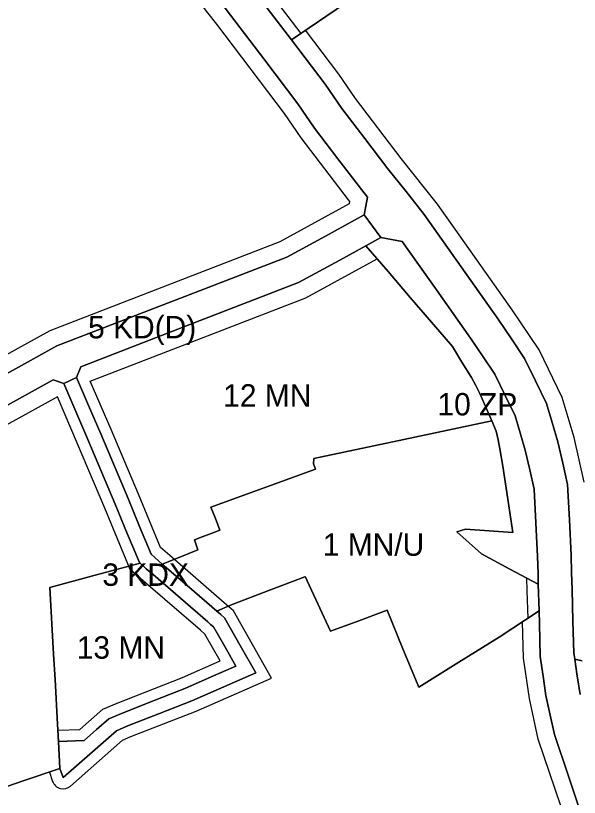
# Model space of a CAD drawing. Extents: x 7423691 to 7425475, y 5552085 to 5554331.
# Drawn here: x 7424385.3 to 7424586.6, y 5552384.7 to 5552663.9 of the extents above; entities that cross this region are included whole.
import ezdxf

# ---------------------------------------------------------------- set-up
doc = ezdxf.new("R2010")
doc.units = 0
for name, color, linetype in [('linia_zabudowy_nieprzekraczalna', 7, 'Continuous'), ('linie_rozgraniczajace', 7, 'Continuous'), ('oznaczenia_przeznaczen', 7, 'Continuous')]:
    doc.layers.add(name, color=color, linetype=linetype)

msp = doc.modelspace()

# ---------------------------------------------------------------- linework, layer by layer
at = {"layer": 'linia_zabudowy_nieprzekraczalna'}
for points in [[(7424378.95, 5552840.23), (7424386.33, 5552813.96), (7424395.24, 5552774.37), (7424402.55, 5552750.36), (7424407.19, 5552738.02), (7424416.77, 5552717.96), (7424423.18, 5552706.49), (7424436.27, 5552687.89), (7424453.78, 5552664.96), (7424456.99, 5552660.89), (7424481.21, 5552628.98), (7424487.16, 5552620.28), (7424504.05, 5552598.12), (7424504.53, 5552597.51), (7424504.36, 5552596.69), (7424479.58, 5552583.13), (7424397.48, 5552551.4), (7424333.75, 5552516.27)], [(7424434.7, 5552731.45), (7424436.32, 5552728.07), (7424441.82, 5552718.22), (7424454.01, 5552700.91), (7424471.16, 5552678.45), (7424474.39, 5552674.35), (7424487.13, 5552657.57)], [(7424588.36, 5552497.25), (7424584.74, 5552513.23), (7424580.52, 5552527.54), (7424572.26, 5552544.52), (7424562.6, 5552558.89), (7424536, 5552596.56), (7424522.97, 5552612.88), (7424506.62, 5552634.34), (7424500.68, 5552643.02), (7424488.78, 5552658.7)], [(7424404.9, 5552388.73), (7424423.44, 5552405.07), (7424426.46, 5552406.37), (7424449.78, 5552415.52), (7424476.7, 5552427.27), (7424463.04, 5552451.36), (7424459.75, 5552454.21), (7424440.29, 5552471.03), (7424436.98, 5552473.92), (7424429.13, 5552492.94), (7424419.34, 5552516.1), (7424411.91, 5552533.39), (7424488.87, 5552563.13), (7424514.37, 5552577.09)], [(7424400.4, 5552408.64), (7424408.18, 5552408.95), (7424416.39, 5552416.19), (7424421.51, 5552418.39), (7424444.81, 5552427.53), (7424458.27, 5552433.41), (7424452.84, 5552443), (7424451.24, 5552444.38), (7424431.75, 5552461.23), (7424426.13, 5552466.13), (7424417.13, 5552487.94), (7424407.39, 5552511.01), (7424400.18, 5552527.77), (7424354.16, 5552502.4)], [(7424568.27, 5552448.72), (7424568.01, 5552458.45), (7424567.89, 5552463.01)], [(7424580.08, 5552381.26), (7424571.92, 5552405.53), (7424568.75, 5552420), (7424566.65, 5552434.46), (7424566.31, 5552447.41)], [(7424397.31, 5552393.73), (7424398.48, 5552390.4)]]:
    msp.add_lwpolyline(points, dxfattribs=at)
msp.add_arc((7424402.25, 5552391.73), 4, 199.4247, 311.4135, dxfattribs=at)
at = {"layer": 'linie_rozgraniczajace'}
for points in [[(7424506.02, 5552670.56), (7424483.83, 5552655.3), (7424471.23, 5552671.9)], [(7424471.23, 5552671.9), (7424483.83, 5552655.3), (7424495.81, 5552639.51), (7424501.75, 5552630.82), (7424510, 5552620)], [(7424483.83, 5552655.3), (7424506.02, 5552670.56)], [(7424458.52, 5552668.64), (7424473.91, 5552648.52), (7424486.08, 5552632.49), (7424492.02, 5552623.79), (7424500.4, 5552612.8), (7424508.78, 5552601.81), (7424510.96, 5552599.07), (7424510.33, 5552595.92), (7424509.69, 5552592.76), (7424495.9, 5552585.22), (7424482.12, 5552577.67), (7424441.07, 5552561.81), (7424400.02, 5552545.95), (7424375.69, 5552532.54)], [(7424586.19, 5552381.92), (7424582.58, 5552392.65), (7424577.71, 5552407.13), (7424576.18, 5552414.1), (7424574.66, 5552421.08), (7424573.65, 5552428.03), (7424572.64, 5552434.97), (7424572.32, 5552446.77), (7424572.2, 5552451.34), (7424571.95, 5552460.83), (7424571.85, 5552464.65), (7424571.68, 5552470.73), (7424571.07, 5552482.76), (7424570.46, 5552494.79), (7424568.89, 5552501.74), (7424567.31, 5552508.69), (7424565.49, 5552514.85), (7424563.68, 5552521.01), (7424560.15, 5552528.26), (7424556.43, 5552535.81), (7424552.2, 5552542.1), (7424547.78, 5552548.68), (7424535.57, 5552565.97), (7424523.36, 5552583.26), (7424515.75, 5552584.68), (7424509.69, 5552592.76), (7424510.33, 5552595.92), (7424510.96, 5552599.07), (7424508.78, 5552601.81), (7424500.4, 5552612.8), (7424492.02, 5552623.79), (7424486.08, 5552632.49), (7424473.91, 5552648.52), (7424458.52, 5552668.64)], [(7424531.2, 5552592.95), (7424524.72, 5552601.07), (7424518.24, 5552609.19), (7424510, 5552620), (7424501.75, 5552630.82), (7424495.81, 5552639.51), (7424483.83, 5552655.3)], [(7424510, 5552620), (7424518.24, 5552609.19), (7424524.72, 5552601.07), (7424531.2, 5552592.95), (7424544.43, 5552574.22), (7424557.66, 5552555.49), (7424562.35, 5552548.5), (7424567.05, 5552541.52), (7424570.98, 5552533.44), (7424574.9, 5552525.36), (7424576.92, 5552518.54), (7424578.93, 5552511.71), (7424580.66, 5552504.07), (7424582.4, 5552496.43), (7424583.03, 5552483.81), (7424583.67, 5552471.2), (7424583.84, 5552465.04), (7424584.01, 5552458.88), (7424584.31, 5552447.58), (7424584.61, 5552436.27), (7424584.83, 5552434.77), (7424584.95, 5552434.02), (7424585.73, 5552428.86), (7424586.86, 5552421.44)], [(7424587.67, 5552433.41), (7424584.95, 5552434.02), (7424584.83, 5552434.77), (7424584.61, 5552436.27), (7424584.31, 5552447.58), (7424584.01, 5552458.88), (7424583.84, 5552465.04), (7424583.67, 5552471.2), (7424583.03, 5552483.81), (7424582.4, 5552496.43), (7424580.66, 5552504.07), (7424578.93, 5552511.71), (7424576.92, 5552518.54), (7424574.9, 5552525.36), (7424570.98, 5552533.44), (7424567.05, 5552541.52), (7424562.35, 5552548.5), (7424557.66, 5552555.49), (7424544.43, 5552574.22), (7424531.2, 5552592.95)], [(7424377.97, 5552522.38), (7424398.69, 5552533.8), (7424402.5, 5552532.49), (7424406.78, 5552522.53), (7424411.07, 5552512.57), (7424415.95, 5552501.03), (7424420.83, 5552489.48), (7424425.15, 5552479), (7424429.47, 5552468.53), (7424429.7, 5552468.32), (7424413.62, 5552464), (7424397.53, 5552459.68), (7424398.84, 5552435.81), (7424399.36, 5552426.8), (7424400.23, 5552410.86), (7424400.56, 5552404.64), (7424401.09, 5552395.05), (7424388.29, 5552390.66), (7424375.49, 5552386.27)], [(7424375.49, 5552386.27), (7424388.29, 5552390.66), (7424401.09, 5552395.05), (7424402.25, 5552391.73), (7424411.76, 5552400.11), (7424421.27, 5552408.49), (7424424.94, 5552410.07), (7424436.6, 5552414.64), (7424448.25, 5552419.21), (7424459.64, 5552424.19), (7424471.03, 5552429.16), (7424465.47, 5552438.98), (7424459.9, 5552448.79), (7424458.52, 5552449.99), (7424457.13, 5552451.19), (7424462.03, 5552453.37), (7424475.29, 5552458.44), (7424488.61, 5552463.52), (7424488.67, 5552463.54), (7424493.15, 5552453.84), (7424497.7, 5552444.03), (7424507.81, 5552447.76), (7424517.92, 5552451.5), (7424523.57, 5552437.79), (7424529.22, 5552424.08), (7424543.61, 5552432.97), (7424558.01, 5552441.87), (7424572.2, 5552451.34), (7424572.32, 5552446.77), (7424572.64, 5552434.97), (7424573.65, 5552428.03), (7424574.66, 5552421.08), (7424576.18, 5552414.1), (7424577.71, 5552407.13), (7424582.58, 5552392.65), (7424586.19, 5552381.92)], [(7424586.86, 5552421.44), (7424585.73, 5552428.86), (7424584.95, 5552434.02), (7424587.67, 5552433.41)]]:
    msp.add_lwpolyline(points, dxfattribs=at)
for points in [[(7424351.36, 5552519.13), (7424375.69, 5552532.54), (7424400.02, 5552545.95), (7424441.07, 5552561.81), (7424482.12, 5552577.67), (7424495.9, 5552585.22), (7424509.69, 5552592.76), (7424515.75, 5552584.68), (7424510.38, 5552581.74), (7424501.04, 5552576.63), (7424486.34, 5552568.58), (7424447.47, 5552553.56), (7424408.6, 5552538.54), (7424406.99, 5552534.71), (7424402.5, 5552532.49), (7424398.69, 5552533.8), (7424377.97, 5552522.38), (7424357.25, 5552510.96), (7424358.03, 5552511.76), (7424353.43, 5552519.46)], [(7424510.38, 5552581.74), (7424515.75, 5552584.68), (7424523.36, 5552583.26), (7424535.57, 5552565.97), (7424547.78, 5552548.68), (7424552.2, 5552542.1), (7424556.43, 5552535.81), (7424560.15, 5552528.26), (7424563.68, 5552521.01), (7424565.49, 5552514.85), (7424567.31, 5552508.69), (7424568.89, 5552501.74), (7424570.46, 5552494.79), (7424571.07, 5552482.76), (7424571.68, 5552470.73), (7424571.85, 5552464.65), (7424571.95, 5552460.83), (7424561.82, 5552466.26), (7424551.7, 5552471.69), (7424542.8, 5552479.58), (7424545.92, 5552480.46), (7424554.41, 5552479.9), (7424562.9, 5552479.35), (7424561.07, 5552491.2), (7424559.24, 5552503.05), (7424558.24, 5552509.18), (7424557.58, 5552512.35), (7424556.91, 5552515.52), (7424555.34, 5552519.22), (7424552.77, 5552525.12), (7424551.07, 5552528.97), (7424549.58, 5552531.83), (7424548.08, 5552534.69), (7424544.68, 5552540.2), (7424541.29, 5552545.72), (7424533.76, 5552554.5), (7424526.23, 5552563.27), (7424518.3, 5552572.51)], [(7424406.99, 5552534.71), (7424408.6, 5552538.54), (7424447.47, 5552553.56), (7424486.34, 5552568.58), (7424501.04, 5552576.63), (7424510.38, 5552581.74), (7424518.3, 5552572.51), (7424526.23, 5552563.27), (7424533.76, 5552554.5), (7424541.29, 5552545.72), (7424544.68, 5552540.2), (7424548.08, 5552534.69), (7424549.58, 5552531.83), (7424551.07, 5552528.97), (7424552.77, 5552525.12), (7424555.34, 5552519.22), (7424523.9, 5552512.56), (7424491.74, 5552505.74), (7424491.71, 5552503.78), (7424492.42, 5552501.97), (7424473.71, 5552495.17), (7424455.01, 5552488.36), (7424456.62, 5552484.27), (7424458.23, 5552480.19), (7424455.07, 5552478.95), (7424451.91, 5552477.71), (7424449.1, 5552476.64), (7424449.73, 5552474.87), (7424450.37, 5552473.1), (7424443.87, 5552470.5), (7424437.66, 5552468.01), (7424433.64, 5552471.52), (7424429.54, 5552481.46), (7424425.44, 5552491.4), (7424420.55, 5552502.97), (7424415.66, 5552514.53), (7424411.33, 5552524.62)], [(7424400.56, 5552404.64), (7424409.76, 5552405.01), (7424414.16, 5552408.89), (7424418.56, 5552412.77), (7424420.8, 5552413.73), (7424423.03, 5552414.69), (7424434.69, 5552419.26), (7424446.34, 5552423.83), (7424455.14, 5552427.68), (7424463.94, 5552431.52), (7424459.96, 5552438.55), (7424455.98, 5552445.57), (7424454.92, 5552446.49), (7424453.86, 5552447.41), (7424444.12, 5552455.83), (7424434.38, 5552464.24), (7424431.92, 5552466.38), (7424429.7, 5552468.32), (7424429.47, 5552468.53), (7424425.15, 5552479), (7424420.83, 5552489.48), (7424415.95, 5552501.03), (7424411.07, 5552512.57), (7424406.78, 5552522.53), (7424402.5, 5552532.49), (7424406.99, 5552534.71), (7424411.33, 5552524.62), (7424415.66, 5552514.53), (7424420.55, 5552502.97), (7424425.44, 5552491.4), (7424429.54, 5552481.46), (7424433.64, 5552471.52), (7424437.66, 5552468.01), (7424447.4, 5552459.6), (7424457.13, 5552451.19), (7424458.52, 5552449.99), (7424459.9, 5552448.79), (7424465.47, 5552438.98), (7424471.03, 5552429.16), (7424459.64, 5552424.19), (7424448.25, 5552419.21), (7424436.6, 5552414.64), (7424424.94, 5552410.07), (7424421.27, 5552408.49), (7424411.76, 5552400.11), (7424402.25, 5552391.73), (7424401.09, 5552395.05)], [(7424437.66, 5552468.01), (7424443.87, 5552470.5), (7424450.37, 5552473.1), (7424449.73, 5552474.87), (7424449.1, 5552476.64), (7424451.91, 5552477.71), (7424455.07, 5552478.95), (7424458.23, 5552480.19), (7424456.62, 5552484.27), (7424455.01, 5552488.36), (7424473.71, 5552495.17), (7424492.42, 5552501.97), (7424491.71, 5552503.78), (7424491.74, 5552505.74), (7424523.9, 5552512.56), (7424555.34, 5552519.22), (7424556.91, 5552515.52), (7424557.58, 5552512.35), (7424558.24, 5552509.18), (7424559.24, 5552503.05), (7424561.07, 5552491.2), (7424562.9, 5552479.35), (7424554.41, 5552479.9), (7424545.92, 5552480.46), (7424542.8, 5552479.58), (7424551.7, 5552471.69), (7424561.82, 5552466.26), (7424571.95, 5552460.83), (7424572.2, 5552451.34), (7424558.01, 5552441.87), (7424543.61, 5552432.97), (7424529.22, 5552424.08), (7424523.57, 5552437.79), (7424517.92, 5552451.5), (7424507.81, 5552447.76), (7424497.7, 5552444.03), (7424493.15, 5552453.84), (7424488.67, 5552463.54), (7424488.61, 5552463.52), (7424475.29, 5552458.44), (7424462.03, 5552453.37), (7424457.13, 5552451.19), (7424447.4, 5552459.6)], [(7424397.53, 5552459.68), (7424413.62, 5552464), (7424429.7, 5552468.32), (7424431.92, 5552466.38), (7424434.38, 5552464.24), (7424444.12, 5552455.83), (7424453.86, 5552447.41), (7424454.92, 5552446.49), (7424455.98, 5552445.57), (7424459.96, 5552438.55), (7424463.94, 5552431.52), (7424455.14, 5552427.68), (7424446.34, 5552423.83), (7424434.69, 5552419.26), (7424423.03, 5552414.69), (7424420.8, 5552413.73), (7424418.56, 5552412.77), (7424414.16, 5552408.89), (7424409.76, 5552405.01), (7424400.56, 5552404.64), (7424400.23, 5552410.86), (7424399.36, 5552426.8), (7424398.84, 5552435.81)]]:
    msp.add_lwpolyline(points, close=True, dxfattribs=at)

# ---------------------------------------------------------------- texts
at = {"layer": 'oznaczenia_przeznaczen'}
for s, p in [('5 KD(D)', (7424411.14, 5552548.66)), ('12 MN', (7424459.39, 5552524.27)), ('10 ZP', (7424535.92, 5552521.12)), ('1 MN/U', (7424494.95, 5552470.98)), ('3 KDX', (7424416.25, 5552460.24)), ('13 MN', (7424407.09, 5552434.23))]:
    msp.add_text(s, height=8, dxfattribs=at).set_placement(p)

doc.saveas('drawing.dxf')
